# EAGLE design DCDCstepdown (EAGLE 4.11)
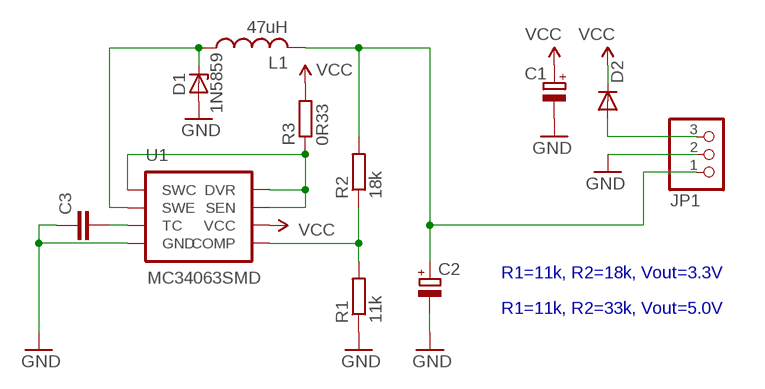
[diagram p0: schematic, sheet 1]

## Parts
C1  CPOL-EUB/3528-21R  [B/3528-21R]
C2  CPOL-EUB/3528-21R  [B/3528-21R]
C3  C-EUC1206  [C1206]
D1  1N5859  ZENER-DIODESMB  [SMB]
D2  DIODE-SMB  [SMB]
JP1  PINHD-1X3  [1X03]
L1  47uH  L-USL1812  [L1812]
R1  11k  R-EU_R1206  [R1206]
R2  18k  R-EU_R1206  [R1206]
R3  0R33  R-EU_R1206  [R1206]
U1  MC34063SMD  [SO08]

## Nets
GND: C1.- C2.- C3.1 D1.A JP1.2 R1.1 U1.4(GND)
N$1: D2.A JP1.3
N$2: C3.2 U1.3(TC)
N$3: D1.C L1.1 U1.2(SWE)
N$4: C2.+ JP1.1 L1.2 R2.2
N$5: R1.2 R2.1 U1.5(COMP)
N$6: R3.1 U1.1(SWC) U1.7(SEN) U1.8(DVR)
VCC: C1.+ D2.C R3.2 U1.6(VCC)

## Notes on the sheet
- R1=11k, R2=18k, Vout=3.3V
- R1=11k, R2=33k, Vout=5.0V

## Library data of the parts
C1 C2 = rcl:CPOL-EU: POLARIZED CAPACITOR, European symbol
C3 = rcl:C-EU: CAPACITOR, European symbol
D1 = diode:ZENER-DIODE: Z-Diode
D2 = diode:DIODE-: DIODE
JP1 = pinhead:PINHD-1X3: PIN HEADER
L1 = rcl:L-US: INDUCTOR, American symbol
R1-R3 = rcl:R-EU_: RESISTOR, European symbol
U1 = SparkFun:MC34063

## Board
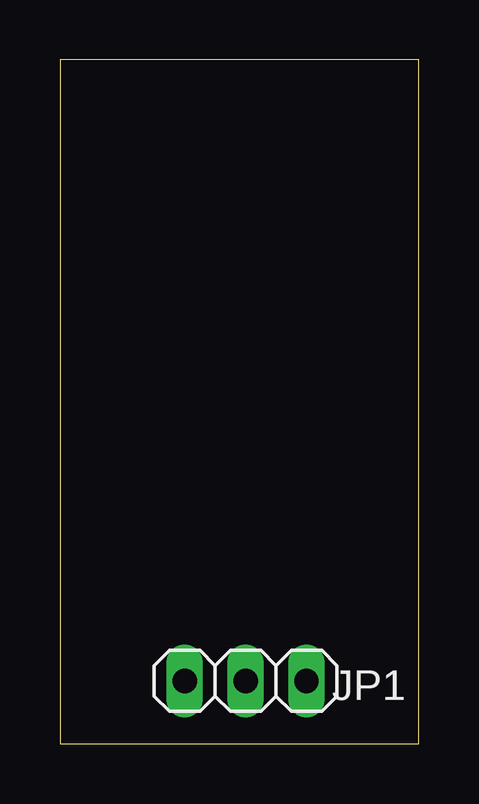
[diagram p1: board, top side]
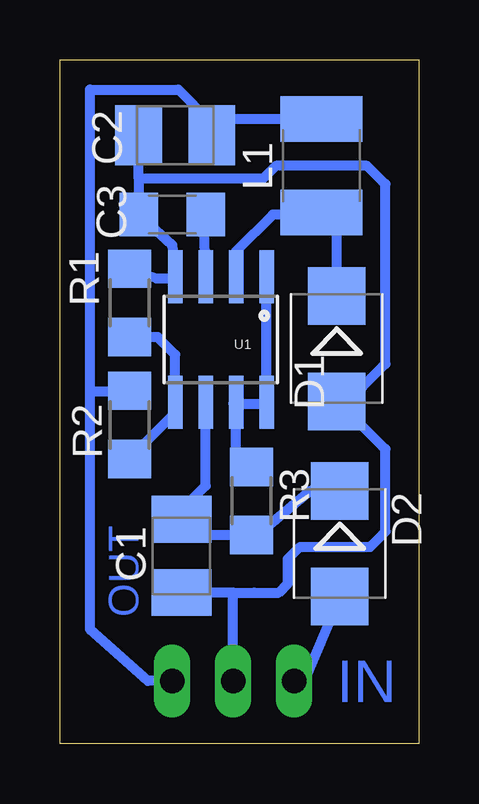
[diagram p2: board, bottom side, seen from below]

Size 14.97 x 28.5 mm. Coordinates in mm from the lower left corner, seen from the top.
Outline: 0,0 14.97,0 14.97,28.5 0,28.5 0,0
Copper layers (1*16): Top 0.035mm / dielectric 1.5mm / Bottom 0.035mm
Design rules "default": minimum track width 10mil, minimum drill 24mil, track to track 8mil, track to pad 8mil, pad to pad 8mil, via to via 8mil, smd to smd 8mil, copper to edge 40mil, drill to drill 8mil, minimum pad ring 10mil, minimum via ring 8mil, stop-mask expansion 4mil, vias tented up to drill 0mil, thermal gap 10mil

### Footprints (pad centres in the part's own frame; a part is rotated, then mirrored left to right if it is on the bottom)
B/3528-21R = smd 1.95 x 2.5: + 1.525,0; - -1.525,0
C1206 = smd 1.6 x 1.8: 1 -1.4,0; 2 1.4,0
SMB = smd 2.4 x 2.4: A 2.2,0; C -2.2,0
1X03 = drill 1.016 long: 1 -2.54,0; 2 0,0; 3 2.54,0
L1812 = smd 1.9 x 3.4: 1 -1.95,0; 2 1.95,0
R1206 = smd 1.6 x 1.803: 1 -1.422,0; 2 1.422,0
SO08 = smd 0.61 x 2.21: 1 -1.905,-2.616; 2 -0.635,-2.616; 3 0.635,-2.616; 4 1.905,-2.616; 5 1.905,2.616; 6 0.635,2.616; 7 -0.635,2.616; 8 -1.905,2.616

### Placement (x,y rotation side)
C1  9.9,7.84 90 bottom
C2  10.16,25.36 0 bottom
C3  10.28,22.06 0 bottom
D1  3.42,16.47 270 bottom
D2  3.3,8.34 270 bottom
JP1  7.74,2.63 180 top
L1  4.06,24.09 90 bottom
R1  12.06,18.38 270 bottom
R2  12.06,13.3 90 bottom
R3  6.98,10.12 270 bottom
U1  8.25,16.85 180 bottom

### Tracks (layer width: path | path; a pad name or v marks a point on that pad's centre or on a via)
GND
  Bottom 0.406: R1.1 10.94,19.39 10.16,19.39 U1.4 10.28,20.79 C3.1 11.68,23.55 | 7.74,6.31 5.84,6.31 5.46,6.69 5.46,7.71 4.95,8.22 2.03,8.22 1.39,8.85 1.39,12.28 3.17,14.06 | 7.74,6.31 C1.- | D1.A 3.42,14.31 3.17,14.06 | 11.68,23.55 C2.- | 11.68,23.55 6.51,23.55 5.96,24.09 2.15,24.09 1.39,23.33 1.39,15.84 3.17,14.06 | 3.17,14.06 3.3,13.93 | 7.74,6.31 6.85,6.31 | JP1.2 7.74,6.31
N$1
  Bottom 0.406: JP1.3 4.82,2.5 3.8,4.91 D2.A
N$2
  Bottom 0.406: C3.2 9.01,22.31 U1.3
N$3
  Bottom 0.406: 4.06,22.06 L1.1 | D1.C 3.42,21.43 4.06,22.06 | U1.2 7.61,20.54 6.09,22.06 4.06,22.06
N$4
  Bottom 0.406: 9.01,24.98 8.88,24.98 8.85,25.04 | 8.85,25.04 C2.+ 7.95,26.04 L1.2 | JP1.1 11.3,2.63 13.71,4.79 13.71,14.69 | R2.2 12.06,14.69 13.71,14.69 | 13.71,14.69 13.71,27.27 10.03,27.27 8.76,26 8.76,25.62 9.14,25.24 8.94,25.04 8.85,25.04
N$5
  Bottom 0.406: R1.2 10.89,16.96 10.16,16.22 U1.5 | U1.5 10.16,14.19 | R2.1 12.06,11.9 10.16,13.8 U1.5
N$6
  Bottom 0.406: U1.1 U1.8 6.4,14.19 7.61,14.19 | 7.67,14.19 7.74,14.19 | 7.67,14.19 U1.7 7.61,14.19 | 7.61,14.19 7.67,14.19 | R3.1 7.61,11.42 7.61,14.19
VCC
  Bottom 0.406: 2.79,10.88 2.83,10.92 D2.C 4.53,10.54 6.85,8.6 6.83,8.7 R3.2 8.73,8.7 10.41,9.49 10.41,9.36 | U1.6 8.88,10.76 10.28,9.36 10.41,9.36 | C1.+ 10.41,9.36 10.28,9.49 10.54,9.36 10.41,9.36

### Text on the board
Bottom: OUT | IN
